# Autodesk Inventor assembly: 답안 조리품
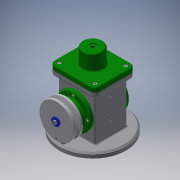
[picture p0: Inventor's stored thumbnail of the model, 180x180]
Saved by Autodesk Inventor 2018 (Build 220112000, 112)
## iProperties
Created: 2019-08
Part Number: 답안 조리품
Document SubType Name: Assembly
Designer: Administrator
Author: Administrator
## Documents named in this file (18)
- C:\Users\Administrator\Desktop\490804V1026\답안 조리품.iam
- C:\Users\Administrator\Desktop\490804V1026\본체.ipt
- C:\Users\Administrator\Desktop\490804V1026\링크.ipt
- C:\Users\Administrator\Desktop\490804V1026\베어링 17 x 40 x 12.ipt
- C:\Users\Administrator\Desktop\490804V1026\볼트 M4 x 8.ipt
- C:\Users\Administrator\Desktop\490804V1026\볼트 M4 x 10.ipt
- C:\Users\Administrator\Desktop\490804V1026\슬라이더.ipt
- C:\Users\Administrator\Desktop\490804V1026\앞커버.ipt
- C:\Users\Administrator\Desktop\490804V1026\오일 실 17 30 8.ipt
- C:\Users\Administrator\Desktop\490804V1026\와셔 4x16.ipt
- C:\Users\Administrator\Desktop\490804V1026\클레비스 핀 6 x 22.ipt
- 클레비스 핀 6 x 22.ipt
- C:\Users\Administrator\Desktop\490804V1026\키 4 x 4 x 12.ipt
- C:\Users\Administrator\Desktop\490804V1026\편심축.ipt
- C:\Users\Administrator\Desktop\490804V1026\V-벨트풀리.ipt
- C:\Users\Administrator\Desktop\490804V1026\덮개.ipt
- C:\Users\Administrator\Desktop\490804V1026\뒤커버.ipt
- C:\Users\Administrator\Desktop\490804V1026\E-링.ipt
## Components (2 placed, 2 different names)
1. V-벨트풀리:1 — 각도:2
2. E-링:1 — 각도:5
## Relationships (2: Angle 2)
- 각도:2 [Angle]: V-벨트풀리:1
- 각도:5 [Angle]: E-링:1
